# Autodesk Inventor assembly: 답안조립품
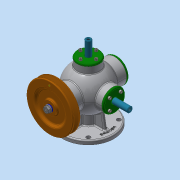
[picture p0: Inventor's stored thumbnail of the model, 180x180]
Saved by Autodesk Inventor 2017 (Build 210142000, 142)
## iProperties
Part Number: 답안조립품
Material: 일반
Document SubType Name: Assembly
Designer: MRC
Mass: 3778.22 g
Surface Area: 2410.88 cm^2
Volume: 904.614 cm^3
Density: 4.17661 g/cm^3
Author: MRC
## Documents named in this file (17)
- C:\Users\MRC\Desktop\600911V1002\답안조립품.iam
- C:\Users\MRC\Desktop\600911V1002\본체.ipt
- C:\Users\MRC\Desktop\600911V1002\Ű 4x4.ipt
- C:\Users\MRC\Desktop\600911V1002\V-벨트풀리.ipt
- C:\Users\MRC\Desktop\600911V1002\너트 M8x1.ipt
- C:\Users\MRC\Desktop\600911V1002\뒤커버.ipt
- C:\Users\MRC\Desktop\600911V1002\베어링 6202.ipt
- C:\Users\MRC\Desktop\600911V1002\본체커버.ipt
- C:\Users\MRC\Desktop\600911V1002\볼트 M4.ipt
- C:\Users\MRC\Desktop\600911V1002\스프링1.ipt
- C:\Users\MRC\Desktop\600911V1002\스프링2.ipt
- C:\Users\MRC\Desktop\600911V1002\슬라이드 커버.ipt
- C:\Users\MRC\Desktop\600911V1002\슬라이드.ipt
- C:\Users\MRC\Desktop\600911V1002\앞커버.ipt
- C:\Users\MRC\Desktop\600911V1002\오일 실.ipt
- C:\Users\MRC\Desktop\600911V1002\와셔 8x17.ipt
- C:\Users\MRC\Desktop\600911V1002\축.ipt
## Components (1 placed, 1 different names)
1. V-벨트풀리:1
